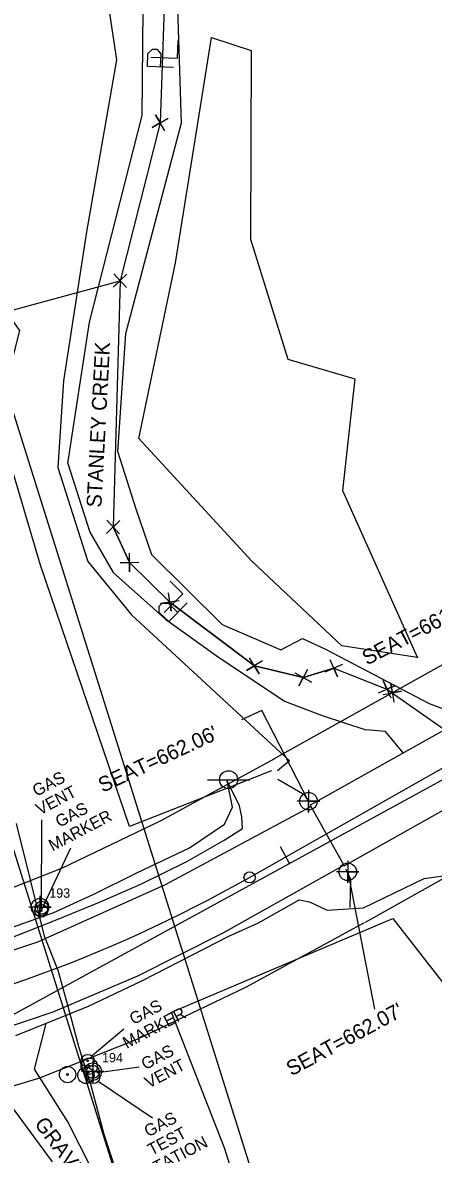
# Model space of a CAD drawing. Extents: x 1380524 to 1382335, y 594765 to 596944.
# Drawn here: x 1381565.9 to 1381675.7, y 595421 to 595723.8 of the extents above; entities that cross this region are included whole.
import ezdxf

# ---------------------------------------------------------------- set-up
doc = ezdxf.new("R2010")
doc.units = 0
for name, color, linetype in [('Exist DTM Regular Point CELL', 7, 'Continuous'), ('Exist Horizontal Alignment', 7, 'Continuous'), ('Exist Horizontal Alignment Station Label', 7, 'Continuous'), ('Exist Horizontal Baseline Alignment', 7, 'Continuous'), ('Exist Horizontal Baseline Alignment Tick small', 7, 'Continuous'), ('Exist Hydro Jurisdictional Stream or Body of Water', 7, 'Continuous'), ('Exist Hydro Jurisdictional Stream or Body of Water Text', 7, 'Continuous'), ('Exist Roads EOP', 7, 'Continuous'), ('Exist Structure Major Bridge Seat Cogo Point CELL', 7, 'Continuous'), ('Exist Structure Major Bridge Seat Top Elevation', 7, 'Continuous'), ('Exist Structure Major Bridge WW', 7, 'Continuous'), ('Exist Utilities Gas UG Line Cogo Number', 7, 'Continuous'), ('Exist Utilities Gas UG Line Cogo Point CELL', 7, 'Continuous'), ('Exist Utilities Gas UG Line SUE', 7, 'Continuous'), ('Exist Utilities Other Located Object Leader', 7, 'Continuous'), ('Exist Utilities Power Tower Text', 7, 'Continuous'), ('Exist Utilities Telephone UG Cable', 7, 'Continuous'), ('Prop Drainage Ditch Boundaries', 7, 'Continuous'), ('Prop Drainage Structure Pipe Elbow CELL', 7, 'Continuous'), ('Prop Earthen Structure Cut Ditch Special Detail CELL', 7, 'Continuous'), ('Prop Earthen Structure Cut Ditch Special Detail Label', 7, 'Continuous'), ('Prop Earthen Structure Ditch Flow Line', 7, 'Continuous'), ('Prop Erosion Rip Rap Pad at Outlet CELL', 7, 'Continuous'), ('Prop Horizontal Alignment Tick Large', 7, 'Continuous'), ('Prop Horizontal Alignment Tick Small', 7, 'Continuous'), ('Prop SS Misc', 7, 'Continuous'), ('Scratch_Level_5', 7, 'Continuous'), ('Scratch_Level_6', 7, 'Continuous')]:
    doc.layers.add(name, color=color, linetype=linetype)

# ---------------------------------------------------------------- blocks, each defined once
blk = doc.blocks.new('EXIST UTILITIES OTHER LOCATED OBJECT')
at = {"layer": 'Prop Earthen Structure Cut Ditch Special Detail CELL'}
for radius in [0.0436, 0.0048]:
    blk.add_circle((0, 0), radius, dxfattribs=at)
blk = doc.blocks.new('EXIST UTILITIES TELEPHONE POLE')
at = {"layer": 'Exist Horizontal Alignment Station Label'}
for p, q in [((-0.1135, 0), (0.11325, 0)), ((0, 0), (0, 0))]:
    blk.add_line(p, q, dxfattribs=at)
blk.add_circle((0, 0), 0.04813, dxfattribs=at)
blk = doc.blocks.new('EXIST DTM REGULAR POINT')
at = {"layer": 'Exist DTM Regular Point CELL'}
blk.add_lwpolyline([(0, 0.06), (0, -0.06), (0, 0), (0.06, 0), (-0.06, 0)], dxfattribs=at)
blk.add_circle((0, 0), 0.0469, dxfattribs=at)

msp = doc.modelspace()

# ---------------------------------------------------------------- linework, layer by layer
at = {"layer": 'Exist Horizontal Alignment'}
msp.add_line((1381626.55, 595495.13), (1381744.58, 595562.07), dxfattribs=at)
msp.add_line((1381626.55, 595495.13), (1381744.58, 595562.07), dxfattribs=at)
msp.add_line((1381626.55, 595495.13), (1381744.58, 595562.07), dxfattribs=at)
msp.add_line((1381626.55, 595495.13), (1381744.58, 595562.07), dxfattribs=at)
msp.add_line((1381626.55, 595495.13), (1381744.58, 595562.07), dxfattribs=at)
msp.add_arc((1381441.55, 595821.31), 375, 279.4361, 299.5612, dxfattribs=at)
msp.add_arc((1381441.55, 595821.31), 375, 279.4361, 299.5612, dxfattribs=at)
msp.add_arc((1381441.55, 595821.31), 375, 279.4361, 299.5612, dxfattribs=at)
at = {"layer": 'Exist Horizontal Alignment Station Label'}
msp.add_circle((1381626.55, 595495.13), 1.5, dxfattribs=at)
at = {"layer": 'Exist Horizontal Baseline Alignment'}
msp.add_line((1381525.59, 595437.8), (1381849.7, 595615.17), dxfattribs=at)
at = {"layer": 'Exist Horizontal Baseline Alignment Tick small'}
msp.add_line((1381637.2, 595498.88), (1381634.8, 595503.26), dxfattribs=at)
at = {"layer": 'Exist Hydro Jurisdictional Stream or Body of Water'}
for p, q in [((1381603.21, 595713.35), (1381603.21, 595713.35)), ((1381591.28, 595608.86), (1381596.18, 595593.76)), ((1381577.96, 595605.83), (1381583.86, 595587.51)), ((1381606.67, 595567.38), (1381606.67, 595567.38)), ((1381640.7, 595559.02), (1381646.87, 595556.21)), ((1381645.98, 595538.45), (1381657.58, 595534.59))]:
    msp.add_line(p, q, dxfattribs=at)
for points in [[(1381577.96, 595605.83), (1381583.71, 595643.65), (1381597.79, 595698.93), (1381598.19, 595737), (1381590.93, 595758.1), (1381566.71, 595783.08), (1381549.63, 595827.2), (1381521.68, 595855.93), (1381508.31, 595880.93), (1381498.43, 595922.32), (1381488.98, 595942.12), (1381494.82, 595973.98), (1381493.85, 596010.61), (1381489.16, 596026.09), (1381477.05, 596042.66), (1381466.32, 596071.54), (1381460.24, 596113.74), (1381470.05, 596141.17)], [(1381591.28, 595608.86), (1381593.5, 595640.64), (1381608.3, 595697.05), (1381607.14, 595736.14), (1381600.89, 595770.21), (1381575.06, 595793.44), (1381555.94, 595831.43), (1381528.67, 595862.58), (1381515.5, 595885.72), (1381506.46, 595926.94), (1381508.98, 595973.98), (1381507.81, 596016.05), (1381489.64, 596056.36), (1381476.02, 596075.92), (1381476.25, 596113.98), (1381483.98, 596135.61)], [(1381600.18, 595714.59), (1381607.25, 595714.34), (1381607.41, 595719.06)], [(1381606.24, 595711.79), (1381599.22, 595712.04), (1381599.35, 595715.6), (1381600.56, 595716.72), (1381601.73, 595716.68), (1381602.78, 595715.47), (1381602.66, 595711.91)], [(1381596.18, 595593.76), (1381600.36, 595581.54), (1381619.25, 595562.82), (1381634.92, 595556.05), (1381640.7, 595559.02)], [(1381583.86, 595587.51), (1381590.06, 595576.7), (1381604.09, 595564.19), (1381617.61, 595554.49), (1381635.92, 595542.28), (1381645.98, 595538.45)], [(1381603.7, 595565.98), (1381608.66, 595571.03), (1381605.28, 595574.34)], [(1381609.87, 595568.56), (1381604.95, 595563.55), (1381602.4, 595566.04), (1381602.4, 595567.7), (1381603.21, 595568.53), (1381604.81, 595568.5), (1381607.35, 595566)], [(1381646.87, 595556.21), (1381674.51, 595541.69), (1381680.7, 595539.3), (1381682.35, 595536.63)], [(1381667.64, 595528.41), (1381662.86, 595534.2), (1381657.58, 595534.59)]]:
    msp.add_lwpolyline(points, dxfattribs=at)
at = {"layer": 'Exist Roads EOP'}
for points in [[(1381638.84, 595379.18), (1381451.62, 595975.74)], [(1381605.45, 595368.7), (1381418.22, 595965.25)], [(1381679.58, 595552.82), (1381632.97, 595526.73)], [(1381633.23, 595526.86), (1381602.66, 595510.2), (1381576.4, 595497.62), (1381553.64, 595488.58), (1381529.89, 595481.4), (1381503.48, 595476.28)], [(1381704, 595509.19), (1381657.4, 595483.1)], [(1381657.14, 595482.97), (1381625.41, 595465.67), (1381596.39, 595451.78), (1381570.08, 595441.33), (1381541.87, 595432.81), (1381512.97, 595427.2)]]:
    msp.add_lwpolyline(points, dxfattribs=at)
at = {"layer": 'Exist Structure Major Bridge Seat Top Elevation'}
msp.add_line((1381652.79, 595496.63), (1381659.97, 595459.9), dxfattribs=at)
at = {"layer": 'Exist Structure Major Bridge WW'}
for p, q in [((1381602.63, 595697), (1381602.63, 595697)), ((1381591.94, 595654.76), (1381591.94, 595654.76)), ((1381590.08, 595588.89), (1381590.08, 595588.89)), ((1381594.46, 595579.35), (1381594.46, 595579.35)), ((1381605.22, 595568.79), (1381605.22, 595568.79)), ((1381627.83, 595551.74), (1381627.83, 595551.74)), ((1381649.07, 595551.08), (1381649.07, 595551.08)), ((1381640.9, 595548.57), (1381640.9, 595548.57)), ((1381663.28, 595545.49), (1381663.28, 595545.49)), ((1381664.71, 595544.49), (1381664.71, 595544.49))]:
    msp.add_line(p, q, dxfattribs=at)
for points in [[(1381603.91, 595694.86), (1381601.35, 595699.15), (1381602.63, 595697), (1381600.48, 595695.73), (1381604.78, 595698.28)], [(1381593.65, 595652.95), (1381590.22, 595656.58), (1381591.94, 595654.76), (1381590.12, 595653.05), (1381593.75, 595656.48)], [(1381588.36, 595590.71), (1381591.79, 595587.08), (1381590.08, 595588.89), (1381591.89, 595590.61), (1381588.26, 595587.18)], [(1381596.96, 595579.37), (1381591.96, 595579.33), (1381594.46, 595579.35), (1381594.48, 595576.85), (1381594.43, 595581.85)], [(1381607.7, 595569.14), (1381602.75, 595568.45), (1381605.22, 595568.79), (1381605.57, 595566.32), (1381604.88, 595571.27)], [(1381629.96, 595553.04), (1381625.69, 595550.44), (1381627.83, 595551.74), (1381629.13, 595549.6), (1381626.52, 595553.87)], [(1381642.07, 595550.78), (1381639.72, 595546.36), (1381640.9, 595548.57), (1381643.1, 595547.4), (1381638.69, 595549.74)], [(1381651.37, 595552.08), (1381646.78, 595550.08), (1381649.07, 595551.08), (1381650.07, 595548.79), (1381648.08, 595553.37)], [(1381660.99, 595544.5), (1381665.58, 595546.49), (1381663.28, 595545.49), (1381662.29, 595547.79), (1381664.28, 595543.2)], [(1381662.24, 595544.06), (1381667.17, 595544.92), (1381664.71, 595544.49), (1381664.28, 595546.95), (1381665.13, 595542.03)]]:
    msp.add_lwpolyline(points, dxfattribs=at)
at = {"layer": 'Exist Utilities Gas UG Line Cogo Point CELL'}
for points in [[(1381570.5, 595490.18), (1381570.5, 595484.18), (1381570.5, 595487.18), (1381573.5, 595487.18), (1381567.5, 595487.18)], [(1381584.61, 595446.15), (1381584.61, 595440.15), (1381584.61, 595443.15), (1381587.61, 595443.15), (1381581.61, 595443.15)]]:
    msp.add_lwpolyline(points, dxfattribs=at)
for centre in [(1381570.5, 595487.18), (1381584.61, 595443.15)]:
    msp.add_circle(centre, 2.34, dxfattribs=at)
at = {"layer": 'Exist Utilities Gas UG Line SUE'}
for p, q in [((1381571.71, 595479.42), (1381564.26, 595509.53)), ((1381575.39, 595470.23), (1381571.71, 595479.42)), ((1381578.03, 595460.58), (1381575.39, 595470.23)), ((1381580.99, 595449.51), (1381578.03, 595460.58)), ((1381584.11, 595439.72), (1381580.99, 595449.51)), ((1381587.69, 595426.36), (1381584.11, 595439.72)), ((1381590.79, 595416.83), (1381587.69, 595426.36))]:
    msp.add_line(p, q, dxfattribs=at)
at = {"layer": 'Exist Utilities Other Located Object Leader'}
for points in [[(1381570.96, 595487.01), (1381571.04, 595510.56)], [(1381570.86, 595486.19), (1381578.73, 595503.06)], [(1381584.45, 595447.43), (1381592.94, 595454.61)], [(1381586.69, 595443.04), (1381597.01, 595444.43)], [(1381586.35, 595440.46), (1381600.58, 595430.83)]]:
    msp.add_lwpolyline(points, dxfattribs=at)
at = {"layer": 'Exist Utilities Power Tower Text'}
for p, q in [((1381603.82, 595730.58), (1381602.63, 595697)), ((1381602.63, 595697), (1381591.94, 595654.76)), ((1381276.88, 595568.76), (1381591.94, 595654.76)), ((1381591.94, 595654.76), (1381590.08, 595588.89)), ((1381590.08, 595588.89), (1381594.46, 595579.35)), ((1381594.46, 595579.35), (1381605.22, 595568.79)), ((1381605.22, 595568.79), (1381627.83, 595551.74)), ((1381627.83, 595551.74), (1381640.9, 595548.57)), ((1381640.9, 595548.57), (1381649.07, 595551.08)), ((1381649.07, 595551.08), (1381663.28, 595545.49)), ((1381663.28, 595545.49), (1381664.71, 595544.49))]:
    msp.add_line(p, q, dxfattribs=at)
at = {"layer": 'Exist Utilities Telephone UG Cable'}
for p, q in [((1381621.94, 595513.87), (1381620.59, 595520.92)), ((1381623.82, 595514.25), (1381620.59, 595520.92)), ((1381624.48, 595511.31), (1381623.82, 595514.25)), ((1381619.86, 595509.33), (1381621.94, 595513.87)), ((1381624.69, 595508.23), (1381624.48, 595511.31)), ((1381610.47, 595503.03), (1381619.86, 595509.33)), ((1381619.78, 595505.05), (1381624.69, 595508.23)), ((1381609.79, 595499.4), (1381619.78, 595505.05)), ((1381596.44, 595496.33), (1381610.47, 595503.03)), ((1381597.43, 595493.29), (1381609.79, 595499.4)), ((1381584.95, 595490.62), (1381596.44, 595496.33)), ((1381586.45, 595488.51), (1381597.43, 595493.29)), ((1381657.02, 595487), (1381673.21, 595494.83)), ((1381673.21, 595494.83), (1381680.78, 595495.88)), ((1381574.25, 595485.72), (1381584.95, 595490.62)), ((1381575.09, 595483.9), (1381586.45, 595488.51)), ((1381628.95, 595482.93), (1381639.84, 595489.09)), ((1381639.84, 595489.09), (1381642.52, 595488.6)), ((1381642.52, 595488.6), (1381647.32, 595486.4)), ((1381647.32, 595486.4), (1381657.02, 595487)), ((1381558.21, 595480.11), (1381574.25, 595485.72)), ((1381559.54, 595477.68), (1381575.09, 595483.9)), ((1381620.96, 595479.39), (1381628.95, 595482.93)), ((1381597.88, 595467.5), (1381620.96, 595479.39)), ((1381583.47, 595460.69), (1381597.88, 595467.5)), ((1381564.06, 595452.79), (1381583.47, 595460.69))]:
    msp.add_line(p, q, dxfattribs=at)
at = {"layer": 'Prop Drainage Ditch Boundaries'}
for points in [[(1381686.52, 595538.96), (1381642.72, 595514.47), (1381651.83, 595498.26)], [(1381651.83, 595498.26), (1381695.38, 595522.78), (1381686.52, 595538.96)]]:
    msp.add_lwpolyline(points, dxfattribs=at)
at = {"layer": 'Prop Drainage Structure Pipe Elbow CELL'}
for points in [[(1381627.85, 595237.32), (1381616.38, 595296.16), (1381610.74, 595339.43), (1381601.64, 595378.09), (1381590.83, 595404.39), (1381578, 595429.72), (1381569.01, 595443.84), (1381572.14, 595456.07)], [(1381573.88, 595419.06), (1381559.15, 595438.88), (1381546.39, 595446.88)]]:
    msp.add_lwpolyline(points, dxfattribs=at)
at = {"layer": 'Prop Earthen Structure Cut Ditch Special Detail Label'}
for points in [[(1381632.41, 595523.63), (1381594.41, 595508.73), (1381570.64, 595578.64), (1381559.09, 595617.64), (1381565.11, 595641.47), (1381533.98, 595685.28), (1381511.68, 595722.95), (1381489.27, 595770.29), (1381496.67, 595816.92), (1381485.72, 595857.08), (1381467.95, 595926.31), (1381480.04, 595973.59), (1381453.92, 595980.31), (1381433.25, 596009.07), (1381415.87, 596065.96), (1381400.69, 596114.25), (1381387.34, 596153.1)], [(1381465.14, 596147.24), (1381454.4, 596115.71), (1381460.79, 596073.39), (1381474.76, 596036.69), (1381485.85, 596011.46), (1381489.74, 595978.87), (1381483.02, 595940.04), (1381494.86, 595911.17), (1381503.32, 595869.73), (1381526.27, 595838.58), (1381548.46, 595817.76), (1381559.9, 595781.05), (1381585.35, 595751.36), (1381590.99, 595713.84), (1381582.97, 595667.85), (1381576.78, 595627.99), (1381575.28, 595604.8), (1381583.28, 595579.61), (1381595.01, 595565.4), (1381637.18, 595526.27), (1381634, 595523.66)], [(1381671.37, 595553.96), (1381651.23, 595557.07), (1381627.19, 595579.7), (1381596.93, 595612.56), (1381606.76, 595659.51), (1381614.14, 595705.8), (1381616.4, 595719.85), (1381626.97, 595716.4), (1381626.81, 595665.91), (1381636.73, 595633.82), (1381654.69, 595628.48), (1381651.41, 595598.68), (1381671.47, 595553.89)], [(1381605.49, 595459.01), (1381664.85, 595484.17), (1381691.18, 595450.22), (1381713.09, 595414.76), (1381731.32, 595375.66), (1381749.27, 595334.34), (1381755.49, 595326.83), (1381786.26, 595322.65), (1381793.66, 595317.36)], [(1381664.11, 595257.15), (1381645.41, 595340.23), (1381619.92, 595422.48), (1381605.73, 595458.79)]]:
    msp.add_lwpolyline(points, dxfattribs=at)
at = {"layer": 'Prop Earthen Structure Ditch Flow Line'}
for points in [[(1381507.54, 595461.4), (1381539.44, 595467.79), (1381569.9, 595477.86), (1381604.03, 595493.18), (1381642.92, 595514.12)], [(1381509.05, 595442.1), (1381528.14, 595445.39), (1381550.94, 595451.4), (1381574.04, 595459.16), (1381596.63, 595468.8), (1381619.48, 595480.29), (1381651.75, 595498.4)]]:
    msp.add_lwpolyline(points, dxfattribs=at)
at = {"layer": 'Prop Erosion Rip Rap Pad at Outlet CELL'}
for points in [[(1381642.38, 595515.43), (1381641.29, 595517.1), (1381634.08, 595521.34)], [(1381652.16, 595497.38), (1381653.48, 595494.78), (1381653.38, 595487.06)]]:
    msp.add_lwpolyline(points, dxfattribs=at)
at = {"layer": 'Prop SS Misc'}
msp.add_line((1381649.07, 595551.08), (1381640.9, 595548.57), dxfattribs=at)
msp.add_lwpolyline([(1381640.9, 595548.57), (1381627.83, 595551.74), (1381605.22, 595568.79), (1381594.46, 595579.35), (1381590.08, 595588.89)], dxfattribs=at)
at = {"layer": 'Scratch_Level_5'}
msp.add_lwpolyline([(1381649.07, 595551.08), (1381663.28, 595545.49), (1381680.13, 595533.61), (1381690.84, 595515.54), (1381696.74, 595507.76), (1381708.21, 595487.16)], dxfattribs=at)
at = {"layer": 'Scratch_Level_6'}
msp.add_lwpolyline([(1381642.31, 595515.51), (1381629.79, 595539.78), (1381624.35, 595537.25)], dxfattribs=at)

# ---------------------------------------------------------------- block references
at = {"layer": 'Exist Horizontal Alignment Station Label', "xscale": 50, "yscale": 50}
msp.add_blockref('EXIST UTILITIES TELEPHONE POLE', (1381620.94, 595521.27), dxfattribs=at)
at = {"layer": 'Exist Structure Major Bridge Seat Cogo Point CELL', "xscale": 50, "yscale": 50}
for p in [(1381642.31, 595515.51), (1381652.79, 595496.63)]:
    msp.add_blockref('EXIST DTM REGULAR POINT', p, dxfattribs=at)
at = {"layer": 'Prop Earthen Structure Cut Ditch Special Detail CELL'}
for p, xscale, yscale in [((1381570.86, 595486.19), 40, 40), ((1381570.96, 595487.01), 40, 40), ((1381583.26, 595446.02), 40, 40), ((1381577.88, 595442.38), 50, 50), ((1381583.66, 595444.61), 50, 50), ((1381584.66, 595443.08), 40, 40), ((1381582.79, 595442.14), 50, 50), ((1381584.73, 595441.68), 40, 40)]:
    msp.add_blockref('EXIST UTILITIES OTHER LOCATED OBJECT', p, dxfattribs=dict(at, xscale=xscale, yscale=yscale))

# ---------------------------------------------------------------- texts
at = {"layer": 'Exist Hydro Jurisdictional Stream or Body of Water Text'}
msp.add_text('STANLEY CREEK', height=4, rotation=86.9353, dxfattribs=at).set_placement((1381586.91, 595594.02))
at = {"layer": 'Exist Structure Major Bridge Seat Top Elevation'}
for s, rotation, p in [("SEAT=661.43'", 27.7976, (1381657.96, 595551.77)), ("SEAT=662.07'", 28.4268, (1381637.73, 595441.86))]:
    msp.add_text(s, height=4, rotation=rotation, dxfattribs=at).set_placement(p)
at = {"layer": 'Exist Utilities Gas UG Line Cogo Number'}
for s, p in [('193', (1381573, 595489.68)), ('194', (1381587.11, 595445.65))]:
    msp.add_text(s, height=2.5, dxfattribs=at).set_placement(p)
at = {"layer": 'Prop Horizontal Alignment Tick Large'}
msp.add_text('GRAVEL', height=4, rotation=306.6288, dxfattribs=at).set_placement((1381568.86, 595429.16))
at = {"layer": 'Prop Horizontal Alignment Tick Small'}
for s, p in [('GAS', (1381569.56, 595516.64)), ('VENT', (1381570.49, 595511.7)), ('GAS', (1381575.69, 595508.39)), ('MARKER', (1381573.88, 595502.01)), ('MARKER', (1381593.69, 595449.21)), ('GAS', (1381595.5, 595455.59)), ('GAS', (1381598.65, 595443.52)), ('VENT', (1381599.58, 595438.58)), ('GAS', (1381599.43, 595425.55)), ('TEST', (1381600.35, 595420.61)), ('STATION', (1381599.29, 595414.62))]:
    msp.add_text(s, height=3.2, rotation=27.7977, dxfattribs=at).set_placement(p)
at = {"layer": 'Scratch_Level_6'}
msp.add_text("SEAT=662.06'", height=4, rotation=25, dxfattribs=at).set_placement((1381587.25, 595517.74))

doc.saveas('drawing.dxf')
